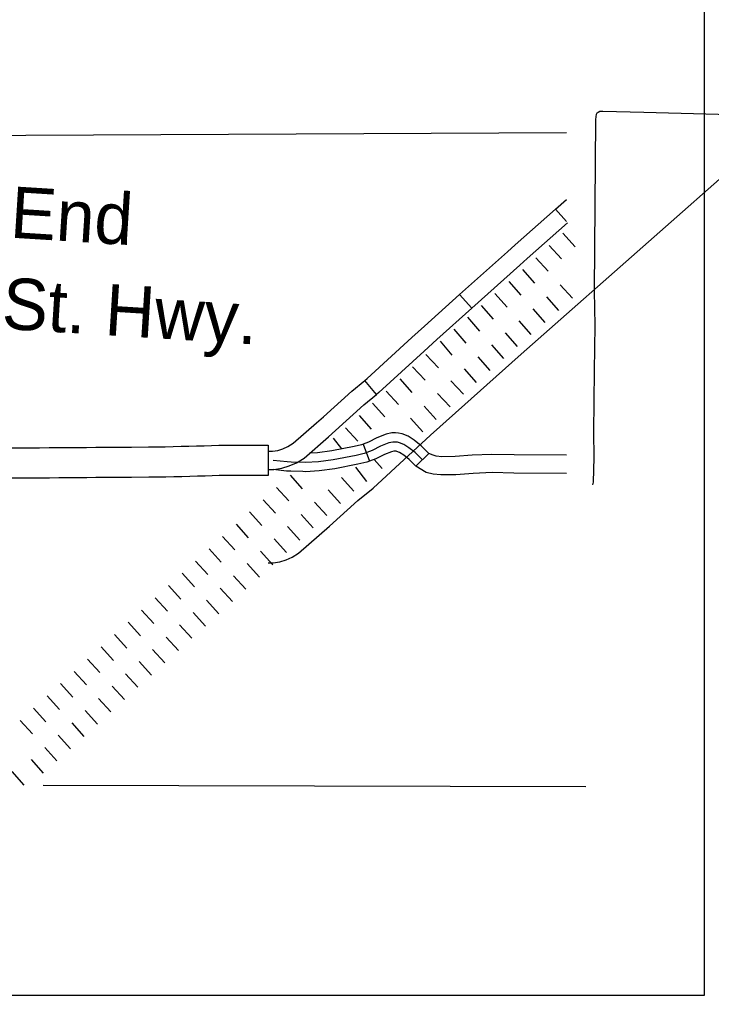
# Model space of a CAD drawing. Extents: x 1366406 to 1373462, y 376856 to 381998.
# Drawn here: x 1369621.8 to 1369714.1, y 379480.6 to 379610.7 of the extents above; entities that cross this region are included whole.
import ezdxf

# ---------------------------------------------------------------- set-up
doc = ezdxf.new("R2010")
doc.units = 0
for name, color, linetype in [('10', 7, 'Continuous'), ('29', 7, 'Continuous'), ('31', 7, 'Continuous'), ('32', 7, 'Continuous'), ('4', 7, 'Continuous'), ('41', 7, 'Continuous'), ('46', 7, 'Continuous'), ('5', 7, 'Continuous'), ('R_No Plot', 7, 'Continuous')]:
    doc.layers.add(name, color=color, linetype=linetype)

msp = doc.modelspace()

# ---------------------------------------------------------------- linework, layer by layer
at = {"layer": '10'}
for points in [[(1369620.73, 379553.57), (1369622.01, 379553.58), (1369623.28, 379553.58), (1369624.53, 379553.59), (1369625.79, 379553.6), (1369627.04, 379553.61), (1369628.3, 379553.63), (1369629.55, 379553.64), (1369630.78, 379553.64), (1369632, 379553.65), (1369633.21, 379553.66), (1369634.41, 379553.67), (1369635.59, 379553.67), (1369636.76, 379553.68), (1369639.04, 379553.7), (1369640.15, 379553.71), (1369641.26, 379553.73), (1369642.34, 379553.75), (1369643.39, 379553.78), (1369644.43, 379553.8), (1369645.45, 379553.83), (1369646.45, 379553.86), (1369647.44, 379553.89), (1369648.4, 379553.91), (1369649.33, 379553.93), (1369650.21, 379553.93), (1369651.04, 379553.93), (1369651.82, 379553.93), (1369652.57, 379553.94), (1369653.26, 379553.94), (1369653.89, 379553.94), (1369654.46, 379553.93), (1369655, 379553.93), (1369654.97, 379549.88)], [(1369654.97, 379549.88), (1369654.44, 379549.88), (1369653.88, 379549.89), (1369653.26, 379549.89), (1369652.58, 379549.89), (1369651.84, 379549.88), (1369651.06, 379549.88), (1369650.22, 379549.88), (1369649.36, 379549.88), (1369648.47, 379549.87), (1369647.54, 379549.84), (1369646.58, 379549.81), (1369645.57, 379549.78), (1369644.54, 379549.75), (1369643.49, 379549.73), (1369642.42, 379549.7), (1369641.33, 379549.68), (1369640.22, 379549.67), (1369639.09, 379549.65), (1369636.79, 379549.63), (1369635.62, 379549.62), (1369634.43, 379549.62), (1369633.24, 379549.61), (1369632.03, 379549.6), (1369630.8, 379549.59), (1369629.57, 379549.59), (1369628.33, 379549.58), (1369627.09, 379549.56), (1369625.83, 379549.55), (1369624.56, 379549.54), (1369623.29, 379549.53), (1369622.02, 379549.53), (1369620.74, 379549.52)]]:
    msp.add_lwpolyline(points, dxfattribs=at)
at = {"layer": '29'}
for p, q in [((1369694.26, 379582.18), (1369695.89, 379580.37)), ((1369692.45, 379580.55), (1369694.08, 379578.75)), ((1369692.45, 379580.55), (1369694.08, 379578.75)), ((1369690.65, 379578.92), (1369692.28, 379577.12)), ((1369688.87, 379577.36), (1369690.47, 379575.53)), ((1369687.04, 379575.76), (1369688.64, 379573.93)), ((1369687.04, 379575.76), (1369688.64, 379573.93)), ((1369693.9, 379575.32), (1369695.53, 379573.51)), ((1369685.21, 379574.16), (1369686.81, 379572.33)), ((1369692.07, 379573.7), (1369693.66, 379571.86)), ((1369683.38, 379572.56), (1369684.98, 379570.73)), ((1369681.55, 379570.97), (1369683.14, 379569.14)), ((1369681.55, 379570.97), (1369683.14, 379569.14)), ((1369690.24, 379572.1), (1369691.83, 379570.27)), ((1369690.24, 379572.1), (1369691.83, 379570.27)), ((1369688.4, 379570.5), (1369690, 379568.67)), ((1369679.72, 379569.37), (1369681.31, 379567.54)), ((1369686.57, 379568.9), (1369688.17, 379567.07)), ((1369677.89, 379567.77), (1369679.48, 379565.94)), ((1369684.74, 379567.3), (1369686.34, 379565.47)), ((1369684.74, 379567.3), (1369686.34, 379565.47)), ((1369676, 379566.03), (1369677.67, 379564.26)), ((1369676, 379566.03), (1369677.67, 379564.26)), ((1369682.91, 379565.71), (1369684.51, 379563.88)), ((1369674.23, 379564.36), (1369675.9, 379562.59)), ((1369681.08, 379564.11), (1369682.68, 379562.28)), ((1369672.51, 379562.76), (1369674.14, 379560.96)), ((1369679.33, 379562.49), (1369681, 379560.72)), ((1369679.33, 379562.49), (1369681, 379560.72)), ((1369670.71, 379561.14), (1369672.33, 379559.33)), ((1369670.71, 379561.14), (1369672.33, 379559.33)), ((1369677.56, 379560.82), (1369679.23, 379559.06)), ((1369668.9, 379559.51), (1369670.53, 379557.7)), ((1369675.76, 379559.15), (1369677.39, 379557.34)), ((1369667.09, 379557.88), (1369668.72, 379556.08)), ((1369673.96, 379557.52), (1369675.58, 379555.72)), ((1369673.96, 379557.52), (1369675.58, 379555.72)), ((1369665.29, 379556.26), (1369666.91, 379554.45)), ((1369665.29, 379556.26), (1369666.91, 379554.45)), ((1369663.66, 379554.88), (1369664.76, 379553.44)), ((1369669.13, 379552), (1369670.17, 379550.84)), ((1369666.61, 379551.02), (1369668.08, 379549.08)), ((1369657.9, 379549.93), (1369659.53, 379548.13)), ((1369664.76, 379549.6), (1369666.4, 379547.81)), ((1369656.1, 379548.3), (1369657.73, 379546.5)), ((1369662.96, 379547.97), (1369664.6, 379546.17)), ((1369662.96, 379547.97), (1369664.6, 379546.17)), ((1369654.3, 379546.66), (1369655.94, 379544.86)), ((1369654.3, 379546.66), (1369655.94, 379544.86)), ((1369661.17, 379546.34), (1369662.8, 379544.54)), ((1369652.5, 379545.03), (1369654.14, 379543.23)), ((1369659.37, 379544.7), (1369661, 379542.9)), ((1369650.7, 379543.39), (1369652.34, 379541.6)), ((1369657.57, 379543.07), (1369659.2, 379541.27)), ((1369657.57, 379543.07), (1369659.2, 379541.27)), ((1369648.91, 379541.76), (1369650.54, 379539.96)), ((1369648.91, 379541.76), (1369650.54, 379539.96)), ((1369655.77, 379541.43), (1369657.41, 379539.63)), ((1369647.11, 379540.13), (1369648.74, 379538.33)), ((1369653.97, 379539.8), (1369655.61, 379538)), ((1369645.31, 379538.49), (1369646.94, 379536.69)), ((1369652.17, 379538.16), (1369653.81, 379536.36)), ((1369652.17, 379538.16), (1369653.81, 379536.36)), ((1369643.51, 379536.86), (1369645.15, 379535.06)), ((1369643.51, 379536.86), (1369645.15, 379535.06)), ((1369650.38, 379536.53), (1369652.01, 379534.73)), ((1369641.71, 379535.22), (1369643.35, 379533.42)), ((1369648.58, 379534.89), (1369650.21, 379533.1)), ((1369639.91, 379533.59), (1369641.55, 379531.79)), ((1369646.78, 379533.26), (1369648.41, 379531.46)), ((1369646.78, 379533.26), (1369648.41, 379531.46)), ((1369638.12, 379531.95), (1369639.75, 379530.16)), ((1369638.12, 379531.95), (1369639.75, 379530.16)), ((1369644.98, 379531.63), (1369646.62, 379529.83)), ((1369636.32, 379530.32), (1369637.95, 379528.52)), ((1369643.18, 379529.99), (1369644.82, 379528.19)), ((1369634.52, 379528.68), (1369636.15, 379526.89)), ((1369641.39, 379528.36), (1369643.02, 379526.56)), ((1369641.39, 379528.36), (1369643.02, 379526.56)), ((1369632.72, 379527.05), (1369634.36, 379525.25)), ((1369632.72, 379527.05), (1369634.36, 379525.25)), ((1369639.59, 379526.72), (1369641.22, 379524.92)), ((1369630.92, 379525.42), (1369632.56, 379523.62)), ((1369637.79, 379525.09), (1369639.42, 379523.29)), ((1369629.13, 379523.78), (1369630.76, 379521.98)), ((1369635.99, 379523.45), (1369637.62, 379521.66)), ((1369635.99, 379523.45), (1369637.62, 379521.66)), ((1369627.33, 379522.15), (1369628.96, 379520.35)), ((1369627.33, 379522.15), (1369628.96, 379520.35)), ((1369634.19, 379521.82), (1369635.83, 379520.02)), ((1369625.53, 379520.51), (1369627.16, 379518.71)), ((1369632.39, 379520.18), (1369634.03, 379518.39)), ((1369623.73, 379518.88), (1369625.36, 379517.08)), ((1369630.6, 379518.55), (1369632.23, 379516.75)), ((1369630.6, 379518.55), (1369632.23, 379516.75)), ((1369621.93, 379517.24), (1369623.57, 379515.45)), ((1369621.93, 379517.24), (1369623.57, 379515.45)), ((1369628.8, 379516.92), (1369630.43, 379515.12)), ((1369627, 379515.28), (1369628.63, 379513.48)), ((1369625.2, 379513.65), (1369626.84, 379511.85)), ((1369625.2, 379513.65), (1369626.84, 379511.85)), ((1369623.39, 379512.02), (1369625.01, 379510.21)), ((1369620.82, 379510.44), (1369622.44, 379508.63))]:
    msp.add_line(p, q, dxfattribs=at)
at = {"layer": '31'}
for p, q in [((1369680.5, 379574.01), (1369682.13, 379572.2)), ((1369669.41, 379560.68), (1369667.87, 379562.56)), ((1369667.87, 379562.56), (1369667.87, 379562.56))]:
    msp.add_line(p, q, dxfattribs=at)
for points in [[(1369654.99, 379538.25), (1369655.64, 379538.24), (1369656.54, 379538.38), (1369657.36, 379538.65), (1369658.19, 379539.01), (1369659.03, 379539.54), (1369663.16, 379543.14), (1369666.93, 379546.57), (1369668.96, 379548.22), (1369676.63, 379555.25), (1369688.68, 379566.06), (1369706.4, 379581.69), (1369717.41, 379591.4), (1369735.95, 379608.31)], [(1369694.75, 379583.74), (1369693.29, 379585.4), (1369694.75, 379586.68)], [(1369686.87, 379579.72), (1369687.88, 379580.62), (1369693.29, 379585.4)], [(1369688.5, 379577.91), (1369689.49, 379578.81), (1369694.89, 379583.57)], [(1369680.5, 379574.01), (1369686.87, 379579.72)], [(1369682.13, 379572.2), (1369688.5, 379577.91)], [(1369674.14, 379568.28), (1369675.82, 379569.81), (1369680.5, 379574.01)], [(1369682.13, 379572.2), (1369677.45, 379568.01), (1369675.78, 379566.48)], [(1369667.87, 379562.56), (1369668.16, 379562.8), (1369674.14, 379568.28)], [(1369675.78, 379566.48), (1369669.75, 379560.96), (1369669.41, 379560.68)], [(1369661.42, 379556.89), (1369662.36, 379557.71), (1369666.14, 379561.14), (1369667.87, 379562.56)], [(1369663.01, 379555.06), (1369663.97, 379555.89), (1369667.72, 379559.3), (1369669.41, 379560.68)], [(1369655, 379553.12), (1369655.55, 379553.11), (1369656.26, 379553.22), (1369656.93, 379553.44), (1369657.62, 379553.74), (1369658.3, 379554.18), (1369661.42, 379556.89)], [(1369654.98, 379550.69), (1369655.72, 379550.68), (1369656.82, 379550.85), (1369657.79, 379551.16), (1369658.76, 379551.59), (1369659.76, 379552.22), (1369663.01, 379555.06)]]:
    msp.add_lwpolyline(points, dxfattribs=at)
at = {"layer": '32'}
for p, q in [((1369667.66, 379554.08), (1369668.49, 379551.8)), ((1369676.41, 379552.84), (1369674.68, 379551.13))]:
    msp.add_line(p, q, dxfattribs=at)
for points in [[(1369771.48, 379596.81), (1369763.64, 379597.01), (1369748, 379597.35), (1369738.44, 379597.6), (1369723.22, 379597.8), (1369705.06, 379598.27), (1369699.58, 379598.4), (1369699.17, 379598.38), (1369698.94, 379598.26), (1369698.79, 379598.16), (1369698.71, 379597.99), (1369698.63, 379597.74), (1369698.59, 379597.31), (1369698.41, 379574.48), (1369698.52, 379569.87), (1369698.43, 379563.84), (1369698.34, 379555.66), (1369698.37, 379552.29), (1369698.27, 379549.01), (1369698.21, 379548.64)], [(1369676.41, 379552.84), (1369675.39, 379553.86), (1369674.44, 379554.58), (1369673.63, 379555.11), (1369672.86, 379555.43), (1369672.37, 379555.54), (1369671.93, 379555.56), (1369671.45, 379555.56), (1369670.71, 379555.4), (1369669.46, 379554.89), (1369668.37, 379554.34), (1369667.66, 379554.08)], [(1369675.54, 379551.98), (1369674.59, 379552.95), (1369673.74, 379553.59), (1369673.06, 379554.03), (1369672.5, 379554.26), (1369672.2, 379554.33), (1369671.9, 379554.35), (1369671.59, 379554.34), (1369671.07, 379554.23), (1369669.96, 379553.79), (1369668.85, 379553.22), (1369667.77, 379552.82), (1369666.69, 379552.57), (1369663.65, 379551.99), (1369661.67, 379551.72), (1369659.96, 379551.6), (1369658.05, 379551.66), (1369657.53, 379551.7), (1369655.64, 379551.89)], [(1369667.66, 379554.08), (1369667.41, 379553.99), (1369666.44, 379553.75), (1369663.45, 379553.19), (1369661.55, 379552.93), (1369660.48, 379552.85)], [(1369674.68, 379551.13), (1369673.79, 379552.03), (1369673.04, 379552.59), (1369672.49, 379552.95), (1369672.13, 379553.1), (1369672.02, 379553.12), (1369671.87, 379553.13), (1369671.73, 379553.13), (1369671.43, 379553.06), (1369670.47, 379552.68), (1369669.34, 379552.1), (1369668.49, 379551.8)], [(1369668.49, 379551.8), (1369668.12, 379551.66), (1369666.95, 379551.38), (1369663.85, 379550.79), (1369661.8, 379550.51), (1369659.98, 379550.39), (1369659.61, 379550.4)], [(1369659.61, 379550.4), (1369658, 379550.45), (1369657.43, 379550.48), (1369655.67, 379550.67)]]:
    msp.add_lwpolyline(points, dxfattribs=at)
at = {"layer": '4'}
msp.add_lwpolyline([(1369694.75, 379595.58), (1369613.62, 379595.17)], dxfattribs=at)
at = {"layer": '46'}
for points in [[(1369694.75, 379552.59), (1369687.78, 379552.64), (1369684.79, 379552.7), (1369682.16, 379552.59), (1369679.9, 379552.42), (1369678.11, 379552.39), (1369677.39, 379552.48), (1369676.95, 379552.59), (1369676.41, 379552.84)], [(1369694.75, 379550.16), (1369687.74, 379550.21), (1369684.82, 379550.27), (1369682.31, 379550.17), (1369680.01, 379549.99), (1369677.98, 379549.96), (1369676.96, 379550.08), (1369676.05, 379550.3), (1369674.68, 379551.13)]]:
    msp.add_lwpolyline(points, dxfattribs=at)
at = {"layer": '5'}
msp.add_lwpolyline([(1369697.31, 379508.39), (1369625, 379508.56)], dxfattribs=at)
at = {"layer": 'R_No Plot'}
for p, q in [((1369713.09, 380368.17), (1369713.09, 379480.59)), ((1369713.09, 379480.59), (1368990.63, 379480.59))]:
    msp.add_line(p, q, dxfattribs=at)

# ---------------------------------------------------------------- texts
at = {"layer": '41'}
for s, p in [('End', (1369620.49, 379581.6)), ('St. Hwy.', (1369619.38, 379569.47))]:
    msp.add_text(s, height=6.843, rotation=356.4139, dxfattribs=at).set_placement(p)

doc.saveas('drawing.dxf')
